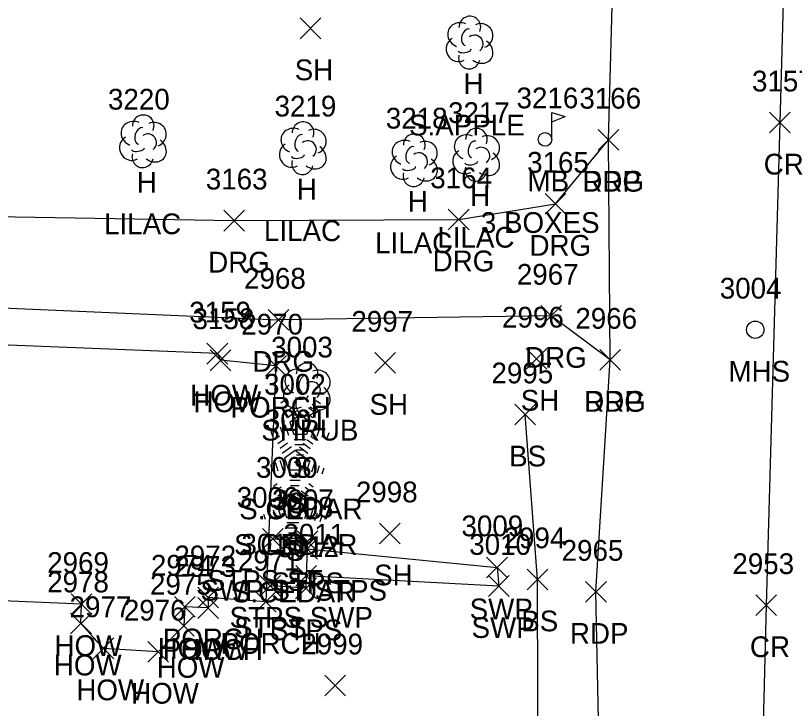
# Model space of a CAD drawing. Extents: x 1609623 to 1616187, y 756677 to 762826.
# Drawn here: x 1610537.9 to 1610613, y 762163.7 to 762230.4 of the extents above; entities that cross this region are included whole.
import ezdxf

# ---------------------------------------------------------------- set-up
doc = ezdxf.new("R2010")
doc.units = 0
for name, color, linetype in [('L_A', 7, 'Continuous'), ('L_C', 7, 'Continuous'), ('L_I', 7, 'Continuous'), ('L_TIC', 7, 'Continuous'), ('LBC', 7, 'Continuous'), ('LBF', 7, 'Continuous'), ('LELB', 7, 'Continuous'), ('LMB', 7, 'Continuous'), ('LSH', 7, 'Continuous'), ('LTC', 7, 'Continuous'), ('LTD', 7, 'Continuous'), ('P_A', 7, 'Continuous'), ('P_I', 7, 'Continuous'), ('P_TIC', 7, 'Continuous'), ('PET', 7, 'Continuous'), ('PRC', 7, 'Continuous'), ('R_A', 7, 'Continuous'), ('R_I', 7, 'Continuous'), ('R_TIC', 7, 'Continuous'), ('RDG', 7, 'Continuous'), ('RSW', 7, 'Continuous'), ('U_A', 7, 'Continuous'), ('U_I', 7, 'Continuous'), ('USMH', 7, 'Continuous')]:
    doc.layers.add(name, color=color, linetype=linetype)

msp = doc.modelspace()

# ---------------------------------------------------------------- linework, layer by layer
at = {"layer": 'L_TIC'}
for points in [[(1610565.324, 762228.161), (1610567.324, 762230.161)], [(1610567.324, 762228.161), (1610565.324, 762230.161)], [(1610556.355, 762196.829), (1610558.355, 762198.829)], [(1610558.355, 762196.829), (1610556.355, 762198.829)], [(1610556.662, 762196.187), (1610558.662, 762198.187)], [(1610558.662, 762196.187), (1610556.662, 762198.187)], [(1610572.533, 762195.938), (1610574.533, 762197.938)], [(1610574.533, 762195.938), (1610572.533, 762197.938)], [(1610587.108, 762196.34), (1610589.108, 762198.34)], [(1610589.108, 762196.34), (1610587.108, 762198.34)], [(1610562.006, 762195.666), (1610564.006, 762197.666)], [(1610564.006, 762195.666), (1610562.006, 762197.666)], [(1610586.033, 762190.967), (1610588.033, 762192.967)], [(1610588.033, 762190.967), (1610586.033, 762192.967)], [(1610572.97, 762179.511), (1610574.97, 762181.511)], [(1610574.97, 762179.511), (1610572.97, 762181.511)], [(1610561.697, 762178.984), (1610563.697, 762180.984)], [(1610563.697, 762178.984), (1610561.697, 762180.984)], [(1610565.046, 762178.757), (1610567.046, 762180.757)], [(1610567.046, 762178.757), (1610565.046, 762180.757)], [(1610565.01, 762178.034), (1610567.01, 762180.034)], [(1610567.01, 762178.034), (1610565.01, 762180.034)], [(1610564.925, 762175.438), (1610566.925, 762177.438)], [(1610566.925, 762175.438), (1610564.925, 762177.438)], [(1610587.202, 762175.086), (1610589.202, 762177.086)], [(1610589.202, 762175.086), (1610587.202, 762177.086)], [(1610561.451, 762174.476), (1610563.451, 762176.476)], [(1610563.451, 762174.476), (1610561.451, 762176.476)], [(1610564.896, 762174.229), (1610566.896, 762176.229)], [(1610566.896, 762174.229), (1610564.896, 762176.229)], [(1610555.476, 762173.348), (1610557.476, 762175.348)], [(1610557.476, 762173.348), (1610555.476, 762175.348)], [(1610543.271, 762172.712), (1610545.271, 762174.712)], [(1610545.271, 762172.712), (1610543.271, 762174.712)], [(1610561.035, 762172.923), (1610563.035, 762174.923)], [(1610563.035, 762172.923), (1610561.035, 762174.923)], [(1610553.216, 762172.447), (1610555.216, 762174.447)], [(1610555.216, 762172.447), (1610553.216, 762174.447)], [(1610555.462, 762172.337), (1610557.462, 762174.337)], [(1610557.462, 762172.337), (1610555.462, 762174.337)], [(1610555.462, 762172.337), (1610557.462, 762174.337)], [(1610557.462, 762172.337), (1610555.462, 762174.337)], [(1610543.214, 762170.839), (1610545.214, 762172.839)], [(1610545.214, 762170.839), (1610543.214, 762172.839)], [(1610553.125, 762170.616), (1610555.125, 762172.616)], [(1610555.125, 762170.616), (1610553.125, 762172.616)], [(1610545.378, 762168.448), (1610547.378, 762170.448)], [(1610547.378, 762168.448), (1610545.378, 762170.448)], [(1610550.658, 762168.122), (1610552.658, 762170.122)], [(1610552.658, 762168.122), (1610550.658, 762170.122)], [(1610567.717, 762164.864), (1610569.717, 762166.864)], [(1610569.717, 762164.864), (1610567.717, 762166.864)]]:
    msp.add_lwpolyline(points, dxfattribs=at)
at = {"layer": 'LBC'}
for points in [[(1610557.662, 762197.187), (1610557.355, 762197.829), (1610526.709, 762199.059)], [(1610544.271, 762173.712), (1610525.977, 762174.475)], [(1610544.214, 762171.839), (1610544.271, 762173.712)], [(1610556.462, 762173.337), (1610554.216, 762173.447), (1610554.125, 762171.616), (1610551.658, 762169.122), (1610546.378, 762169.448), (1610544.214, 762171.839)]]:
    msp.add_lwpolyline(points, dxfattribs=at)
at = {"layer": 'LBF'}
for points in [[(1610563.006, 762196.666), (1610557.662, 762197.187)], [(1610563.006, 762196.666), (1610562.035, 762173.923), (1610556.476, 762174.348), (1610556.462, 762173.337)], [(1610562.697, 762179.984), (1610566.046, 762179.757), (1610566.01, 762179.034), (1610565.925, 762176.438), (1610565.896, 762175.229), (1610562.451, 762175.476)]]:
    msp.add_lwpolyline(points, dxfattribs=at)
at = {"layer": 'LELB'}
msp.add_lwpolyline([(1610588.017, 762127.012), (1610588.281, 762152.993), (1610588.202, 762176.086), (1610587.033, 762191.967)], dxfattribs=at)
at = {"layer": 'LMB'}
for p, q in [((1610589.588, 762221.058), (1610590.881, 762220.676)), ((1610589.594, 762218.465), (1610589.592, 762221.06)), ((1610589.592, 762220.158), (1610590.875, 762220.667)), ((1610588.938, 762218.457), (1610588.938, 762218.457))]:
    msp.add_line(p, q, dxfattribs=at)
msp.add_circle((1610588.938, 762218.457), 0.656, dxfattribs=at)
at = {"layer": 'LSH'}
msp.add_line((1610565.959, 762194.459), (1610565.959, 762194.459), dxfattribs=at)
msp.add_line((1610565.959, 762194.459), (1610565.959, 762194.459), dxfattribs=at)
msp.add_arc((1610566.006, 762195.893), 1.047, 335.52715, 180.95627, dxfattribs=at)
for centre, major_axis, ratio, start_param, end_param in [((1610565.167, 762195.126), (1.21, -0.512), 0.895232, 1.570796, 4.712389), ((1610567.001, 762195.043), (-1.141, -0.483), 0.949671, 1.570796, 4.712389), ((1610565.751, 762194.917), (-0.208, -0.792), 0.645439, 3.141593, 6.283185), ((1610564.876, 762193.751), (0.584, -1.042), 0.959034, 3.141593, 6.283185), ((1610566.459, 762194.293), (-0.5, 0.667), 0.989748, 3.141593, 6.283185), ((1610566.959, 762193.626), (-1.09, 0.792), 0.841452, 1.570796, 4.712389), ((1610565.501, 762193.709), (-0.625, -0.083), 0.423636, 0, 3.141593), ((1610565.959, 762192.959), (0.265, 1.061), 0.942809, 1.570796, 4.712389)]:
    msp.add_ellipse(centre, major_axis=major_axis, ratio=ratio, start_param=start_param, end_param=end_param, dxfattribs=at)
at = {"layer": 'LTC'}
for p, q in [((1610563.474, 762193.083), (1610563.828, 762193.341)), ((1610566.872, 762193.323), (1610567.291, 762193.019)), ((1610563.683, 762192.618), (1610564.212, 762193.002)), ((1610563.893, 762192.152), (1610564.597, 762192.663)), ((1610566.13, 762192.627), (1610566.809, 762192.133)), ((1610566.501, 762192.975), (1610567.05, 762192.576)), ((1610564.102, 762191.686), (1610564.981, 762192.324)), ((1610564.327, 762191.231), (1610565.339, 762191.966)), ((1610565.339, 762191.966), (1610566.336, 762191.241)), ((1610565.759, 762192.278), (1610566.568, 762191.69)), ((1610563.872, 762191.012), (1610564.203, 762189.993)), ((1610564.327, 762191.231), (1610564.714, 762190.038)), ((1610566.336, 762191.241), (1610565.945, 762190.038)), ((1610562.506, 762190.362), (1610562.658, 762189.894)), ((1610562.962, 762190.579), (1610563.173, 762189.927)), ((1610563.417, 762190.796), (1610563.688, 762189.96)), ((1610566.773, 762190.97), (1610566.435, 762189.93)), ((1610567.218, 762190.719), (1610566.93, 762189.835)), ((1610567.662, 762190.469), (1610567.425, 762189.74)), ((1610562.981, 762189.652), (1610563.335, 762189.91)), ((1610563.19, 762189.187), (1610563.719, 762189.571)), ((1610565.945, 762190.038), (1610564.714, 762190.038)), ((1610565.906, 762189.538), (1610564.762, 762189.538)), ((1610566.008, 762189.544), (1610566.557, 762189.145)), ((1610566.379, 762189.893), (1610566.798, 762189.588)), ((1610568.107, 762190.219), (1610567.92, 762189.645)), ((1610563.4, 762188.721), (1610564.104, 762189.232)), ((1610563.609, 762188.255), (1610564.488, 762188.893)), ((1610565.822, 762189.038), (1610564.834, 762189.038)), ((1610565.266, 762188.848), (1610566.075, 762188.259)), ((1610565.637, 762189.196), (1610566.316, 762188.702)), ((1610563.834, 762187.8), (1610564.846, 762188.535)), ((1610564.846, 762188.535), (1610565.843, 762187.81)), ((1610565.739, 762188.538), (1610564.907, 762188.538)), ((1610565.655, 762188.038), (1610564.98, 762188.038)), ((1610562.924, 762187.365), (1610563.195, 762186.529)), ((1610563.379, 762187.581), (1610563.71, 762186.562)), ((1610563.834, 762187.8), (1610564.221, 762186.607)), ((1610565.843, 762187.81), (1610565.451, 762186.607)), ((1610566.28, 762187.539), (1610565.942, 762186.499)), ((1610566.725, 762187.289), (1610566.437, 762186.404)), ((1610562.013, 762186.931), (1610562.165, 762186.464)), ((1610562.469, 762187.148), (1610562.68, 762186.496)), ((1610565.451, 762186.607), (1610564.221, 762186.607)), ((1610567.169, 762187.039), (1610566.932, 762186.309)), ((1610567.614, 762186.788), (1610567.427, 762186.214)), ((1610565.413, 762186.107), (1610564.269, 762186.107)), ((1610562.778, 762185.081), (1610563.133, 762185.339)), ((1610562.988, 762184.616), (1610563.517, 762185)), ((1610565.329, 762185.607), (1610564.341, 762185.607)), ((1610565.246, 762185.107), (1610564.414, 762185.107)), ((1610566.177, 762185.322), (1610566.596, 762185.017)), ((1610563.198, 762184.15), (1610563.901, 762184.661)), ((1610563.407, 762183.684), (1610564.286, 762184.322)), ((1610565.162, 762184.607), (1610564.487, 762184.607)), ((1610565.063, 762184.277), (1610565.873, 762183.688)), ((1610565.435, 762184.625), (1610566.114, 762184.131)), ((1610565.806, 762184.973), (1610566.355, 762184.574)), ((1610563.632, 762183.229), (1610564.643, 762183.964)), ((1610564.643, 762183.964), (1610565.641, 762183.239)), ((1610562.722, 762182.794), (1610562.993, 762181.958)), ((1610563.177, 762183.01), (1610563.508, 762181.991)), ((1610563.632, 762183.229), (1610564.019, 762182.036)), ((1610565.641, 762183.239), (1610565.249, 762182.036)), ((1610566.078, 762182.968), (1610565.74, 762181.928)), ((1610561.811, 762182.36), (1610561.963, 762181.892)), ((1610562.266, 762182.577), (1610562.478, 762181.925)), ((1610565.249, 762182.036), (1610564.019, 762182.036)), ((1610566.523, 762182.717), (1610566.235, 762181.833)), ((1610566.967, 762182.467), (1610566.73, 762181.738)), ((1610567.411, 762182.217), (1610567.225, 762181.643)), ((1610565.211, 762181.536), (1610564.066, 762181.536)), ((1610565.127, 762181.036), (1610564.139, 762181.036)), ((1610565.043, 762180.536), (1610564.212, 762180.536)), ((1610564.96, 762180.036), (1610564.285, 762180.036))]:
    msp.add_line(p, q, dxfattribs=at)
at = {"layer": 'LTD'}
for p, q in [((1610581.643, 762227.839), (1610581.643, 762227.839)), ((1610581.643, 762227.839), (1610581.643, 762227.839)), ((1610550.163, 762218.332), (1610550.163, 762218.332)), ((1610550.163, 762218.332), (1610550.163, 762218.332)), ((1610565.573, 762217.667), (1610565.573, 762217.667)), ((1610565.573, 762217.667), (1610565.573, 762217.667)), ((1610582.28, 762217.04), (1610582.28, 762217.04)), ((1610582.28, 762217.04), (1610582.28, 762217.04)), ((1610576.284, 762216.505), (1610576.284, 762216.505)), ((1610576.284, 762216.505), (1610576.284, 762216.505))]:
    msp.add_line(p, q, dxfattribs=at)
for centre in [(1610581.69, 762229.273), (1610550.21, 762219.766), (1610565.62, 762219.1), (1610582.327, 762218.474), (1610576.331, 762217.939)]:
    msp.add_arc(centre, 1.047, 335.52715, 180.95627, dxfattribs=at)
for centre, major_axis, ratio, start_param, end_param in [((1610580.851, 762228.506), (1.21, -0.512), 0.895232, 1.570796, 4.712389), ((1610582.685, 762228.423), (-1.141, -0.483), 0.949671, 1.570796, 4.712389), ((1610581.435, 762228.298), (-0.208, -0.792), 0.645439, 3.141593, 6.283185), ((1610582.143, 762227.673), (-0.5, 0.667), 0.989748, 3.141593, 6.283185), ((1610580.56, 762227.131), (0.584, -1.042), 0.959034, 3.141593, 6.283185), ((1610582.643, 762227.006), (-1.09, 0.792), 0.841452, 1.570796, 4.712389), ((1610581.185, 762227.089), (-0.625, -0.083), 0.423636, 0, 3.141593), ((1610581.643, 762226.339), (0.265, 1.061), 0.942809, 1.570796, 4.712389), ((1610549.372, 762218.998), (1.21, -0.512), 0.895232, 1.570796, 4.712389), ((1610549.955, 762218.79), (-0.208, -0.792), 0.645439, 3.141593, 6.283185), ((1610551.205, 762218.915), (-1.141, -0.483), 0.949671, 1.570796, 4.712389), ((1610564.781, 762218.333), (1.21, -0.512), 0.895232, 1.570796, 4.712389), ((1610566.615, 762218.25), (-1.141, -0.483), 0.949671, 1.570796, 4.712389), ((1610550.663, 762218.165), (-0.5, 0.667), 0.989748, 3.141593, 6.283185), ((1610565.365, 762218.125), (-0.208, -0.792), 0.645439, 3.141593, 6.283185), ((1610581.488, 762217.706), (1.21, -0.512), 0.895232, 1.570796, 4.712389), ((1610583.321, 762217.623), (-1.141, -0.483), 0.949671, 1.570796, 4.712389), ((1610549.08, 762217.623), (0.584, -1.042), 0.959034, 3.141593, 6.283185), ((1610551.164, 762217.499), (-1.09, 0.792), 0.841452, 1.570796, 4.712389), ((1610566.073, 762217.5), (-0.5, 0.667), 0.989748, 3.141593, 6.283185), ((1610575.492, 762217.172), (1.21, -0.512), 0.895232, 1.570796, 4.712389), ((1610577.325, 762217.089), (-1.141, -0.483), 0.949671, 1.570796, 4.712389), ((1610582.071, 762217.498), (-0.208, -0.792), 0.645439, 3.141593, 6.283185), ((1610549.705, 762217.582), (-0.625, -0.083), 0.423636, 0, 3.141593), ((1610564.49, 762216.958), (0.584, -1.042), 0.959034, 3.141593, 6.283185), ((1610566.573, 762216.833), (-1.09, 0.792), 0.841452, 1.570796, 4.712389), ((1610576.075, 762216.964), (-0.208, -0.792), 0.645439, 3.141593, 6.283185), ((1610576.784, 762216.339), (-0.5, 0.667), 0.989748, 3.141593, 6.283185), ((1610581.197, 762216.331), (0.584, -1.042), 0.959034, 3.141593, 6.283185), ((1610582.78, 762216.873), (-0.5, 0.667), 0.989748, 3.141593, 6.283185), ((1610550.164, 762216.832), (0.265, 1.061), 0.942809, 1.570796, 4.712389), ((1610565.115, 762216.916), (-0.625, -0.083), 0.423636, 0, 3.141593), ((1610575.201, 762215.797), (0.584, -1.042), 0.959034, 3.141593, 6.283185), ((1610577.284, 762215.672), (-1.09, 0.792), 0.841452, 1.570796, 4.712389), ((1610583.28, 762216.206), (-1.09, 0.792), 0.841452, 1.570796, 4.712389), ((1610565.573, 762216.167), (0.265, 1.061), 0.942809, 1.570796, 4.712389), ((1610575.826, 762215.755), (-0.625, -0.083), 0.423636, 0, 3.141593), ((1610582.28, 762215.54), (0.265, 1.061), 0.942809, 1.570796, 4.712389), ((1610581.822, 762216.289), (-0.625, -0.083), 0.423636, 0, 3.141593), ((1610576.284, 762215.005), (0.265, 1.061), 0.942809, 1.570796, 4.712389)]:
    msp.add_ellipse(centre, major_axis=major_axis, ratio=ratio, start_param=start_param, end_param=end_param, dxfattribs=at)
at = {"layer": 'P_TIC'}
for points in [[(1610610.575, 762219.08), (1610612.575, 762221.08)], [(1610612.575, 762219.08), (1610610.575, 762221.08)], [(1610594.042, 762217.426), (1610596.042, 762219.426)], [(1610596.042, 762217.426), (1610594.042, 762219.426)], [(1610594.221, 762196.229), (1610596.221, 762198.229)], [(1610596.221, 762196.229), (1610594.221, 762198.229)], [(1610592.846, 762173.883), (1610594.846, 762175.883)], [(1610594.846, 762173.883), (1610592.846, 762175.883)], [(1610609.25, 762172.6), (1610611.25, 762174.6)], [(1610611.25, 762172.6), (1610609.25, 762174.6)]]:
    msp.add_lwpolyline(points, dxfattribs=at)
at = {"layer": 'PET'}
for points in [[(1610595.042, 762218.426), (1610595.917, 762249.995), (1610597.031, 762268.03), (1610599.193, 762317.836), (1610601.019, 762361.918), (1610601.974, 762392.041), (1610603.581, 762435.722)], [(1610595.221, 762197.229), (1610595.042, 762218.426)], [(1610585.692, 762059.184), (1610595.53, 762075.623), (1610597.332, 762109.675), (1610594.5, 762142.599), (1610593.846, 762174.883), (1610595.221, 762197.229)]]:
    msp.add_lwpolyline(points, dxfattribs=at)
at = {"layer": 'PRC'}
for points in [[(1610616.879, 762447.816), (1610616.899, 762397.767), (1610615.755, 762350.31), (1610614.292, 762312.677), (1610612.908, 762268.601), (1610611.575, 762220.08)], [(1610611.575, 762220.08), (1610610.25, 762173.6)], [(1610610.25, 762173.6), (1610609.383, 762139.192), (1610609.124, 762094.71), (1610608.211, 762046.285), (1610607.395, 761995.029), (1610607.457, 761942.783), (1610607.989, 761912.156), (1610611.007, 761877.324)]]:
    msp.add_lwpolyline(points, dxfattribs=at)
at = {"layer": 'R_TIC'}
for points in [[(1610594.042, 762217.426), (1610596.042, 762219.426)], [(1610596.042, 762217.426), (1610594.042, 762219.426)], [(1610588.951, 762211.253), (1610590.951, 762213.253)], [(1610590.951, 762211.253), (1610588.951, 762213.253)], [(1610557.985, 762209.639), (1610559.985, 762211.639)], [(1610559.985, 762209.639), (1610557.985, 762211.639)], [(1610579.614, 762209.756), (1610581.614, 762211.756)], [(1610581.614, 762209.756), (1610579.614, 762211.756)], [(1610588.527, 762200.466), (1610590.527, 762202.466)], [(1610590.527, 762200.466), (1610588.527, 762202.466)], [(1610562.239, 762200.083), (1610564.239, 762202.083)], [(1610564.239, 762200.083), (1610562.239, 762202.083)], [(1610594.221, 762196.229), (1610596.221, 762198.229)], [(1610596.221, 762196.229), (1610594.221, 762198.229)], [(1610565.01, 762178.034), (1610567.01, 762180.034)], [(1610567.01, 762178.034), (1610565.01, 762180.034)], [(1610583.308, 762176.243), (1610585.308, 762178.243)], [(1610585.308, 762176.243), (1610583.308, 762178.243)], [(1610564.925, 762175.438), (1610566.925, 762177.438)], [(1610566.925, 762175.438), (1610564.925, 762177.438)], [(1610583.493, 762174.45), (1610585.493, 762176.45)], [(1610585.493, 762174.45), (1610583.493, 762176.45)]]:
    msp.add_lwpolyline(points, dxfattribs=at)
at = {"layer": 'RDG'}
for points in [[(1610526.959, 762202.645), (1610528.28, 762211.152), (1610558.985, 762210.639), (1610580.614, 762210.756), (1610589.951, 762212.253), (1610595.042, 762218.426)], [(1610526.959, 762202.645), (1610563.239, 762201.083)], [(1610595.221, 762197.229), (1610589.527, 762201.466), (1610563.239, 762201.083)]]:
    msp.add_lwpolyline(points, dxfattribs=at)
at = {"layer": 'RSW'}
msp.add_lwpolyline([(1610566.01, 762179.034), (1610584.308, 762177.243), (1610584.493, 762175.45), (1610565.925, 762176.438)], dxfattribs=at)
at = {"layer": 'USMH'}
for p, q in [((1610609.195, 762200.133), (1610609.195, 762200.133)), ((1610610.028, 762200.133), (1610610.028, 762200.133))]:
    msp.add_line(p, q, dxfattribs=at)
msp.add_circle((1610609.195, 762200.133), 0.833, dxfattribs=at)

# ---------------------------------------------------------------- texts
at = {"layer": 'L_A'}
for s, p in [('SH', (1610564.812, 762224.161)), ('H', (1610581.076, 762222.839)), ('H', (1610549.596, 762213.332)), ('MB', (1610587.245, 762213.457)), ('H', (1610565.006, 762212.667)), ('H', (1610581.713, 762212.04)), ('H', (1610575.717, 762211.505)), ('HOW', (1610554.741, 762192.829)), ('HOW', (1610555.048, 762192.187)), ('SH', (1610586.596, 762192.34)), ('PORCH', (1610558.628, 762191.666)), ('SH', (1610572.021, 762191.938)), ('SHRUB', (1610561.589, 762189.459)), ('BS', (1610585.474, 762186.967)), ('S', (1610564.664, 762185.875)), ('S', (1610564.171, 762182.444)), ('S', (1610563.969, 762177.873)), ('SH', (1610572.458, 762175.511)), ('STPS ST', (1610556.342, 762174.984)), ('STPS', (1610562.566, 762174.757)), ('SWP ST STPS', (1610555.726, 762174.034)), ('STPS SWP', (1610558.531, 762171.438)), ('BS', (1610586.643, 762171.086)), ('STPS', (1610558.971, 762170.476)), ('STPS', (1610562.416, 762170.229)), ('HOW', (1610541.657, 762168.712)), ('PORCH', (1610552.098, 762169.348)), ('PORCH', (1610557.657, 762168.923)), ('HOW', (1610551.602, 762168.447)), ('PORCH', (1610552.084, 762168.337)), ('HOW', (1610553.847, 762168.337)), ('HOW', (1610541.599, 762166.839)), ('HOW', (1610551.511, 762166.616)), ('HOW', (1610543.764, 762164.448)), ('HOW', (1610549.044, 762164.122))]:
    msp.add_text(s, height=2, dxfattribs=at).set_placement(p)
at = {"layer": 'L_C'}
for s, p in [('S.APPLE', (1610575.832, 762218.839)), ('LILAC', (1610546.439, 762209.332)), ('3 BOXES', (1610582.749, 762209.457)), ('LILAC', (1610561.849, 762208.667)), ('LILAC', (1610578.555, 762208.04)), ('LILAC', (1610572.559, 762207.505)), ('S.CEDAR', (1610559.46, 762181.875)), ('S.CEDAR', (1610558.967, 762178.444)), ('S.CEDAR', (1610558.764, 762173.873))]:
    msp.add_text(s, height=2, dxfattribs=at).set_placement(p)
at = {"layer": 'L_I'}
for s, p in [('3220', (1610546.817, 762221.332)), ('3216', (1610586.19, 762221.457)), ('3219', (1610562.872, 762220.667)), ('3217', (1610579.587, 762220.04)), ('3218', (1610573.591, 762219.505)), ('3159', (1610554.654, 762200.829)), ('2996', (1610584.793, 762200.34)), ('3158', (1610554.969, 762200.187)), ('2970', (1610559.659, 762199.666)), ('2997', (1610570.273, 762199.938)), ('3003', (1610562.542, 762197.459)), ('2995', (1610583.773, 762194.967)), ('3002', (1610561.861, 762193.875)), ('3001', (1610561.935, 762190.444)), ('3000', (1610561.079, 762185.873)), ('3006', (1610559.224, 762182.984)), ('2998', (1610570.71, 762183.511)), ('3007', (1610562.629, 762182.757)), ('3008', (1610562.592, 762182.034)), ('3011', (1610563.72, 762179.438)), ('3013', (1610559.679, 762178.476)), ('2994', (1610584.943, 762179.086)), ('3012', (1610563.125, 762178.229)), ('2972', (1610553.216, 762177.348)), ('2969', (1610540.956, 762176.712)), ('2974', (1610550.956, 762176.447)), ('2973', (1610553.202, 762176.337)), ('2973', (1610553.202, 762176.337)), ('2971', (1610559.342, 762176.923)), ('2978', (1610540.954, 762174.839)), ('2975', (1610550.865, 762174.616)), ('2977', (1610543.118, 762172.448)), ('2976', (1610548.343, 762172.122)), ('2999', (1610565.449, 762168.864))]:
    msp.add_text(s, height=2, dxfattribs=at).set_placement(p)
at = {"layer": 'LTC'}
for p in [(1610565.221, 762190.979), (1610564.728, 762187.548), (1610564.526, 762182.977)]:
    msp.add_text('.', height=1.037, rotation=270, dxfattribs=at).set_placement(p)
at = {"layer": 'P_A'}
for s, p in [('CR', (1610610.008, 762215.08)), ('RDP', (1610592.53, 762213.426)), ('RDP', (1610592.709, 762192.229)), ('RDP', (1610591.334, 762169.883)), ('CR', (1610608.683, 762168.6))]:
    msp.add_text(s, height=2, dxfattribs=at).set_placement(p)
at = {"layer": 'P_I'}
for s, p in [('3157', (1610608.882, 762223.08)), ('3166', (1610592.247, 762221.426)), ('2966', (1610591.859, 762200.229)), ('2965', (1610590.539, 762177.883)), ('2953', (1610606.99, 762176.6))]:
    msp.add_text(s, height=2, dxfattribs=at).set_placement(p)
at = {"layer": 'R_A'}
for s, p in [('DRG', (1610592.53, 762213.426)), ('DRG', (1610587.439, 762207.253)), ('DRG', (1610556.473, 762205.639)), ('DRG', (1610578.102, 762205.756)), ('DRG', (1610560.727, 762196.083)), ('DRG', (1610587.015, 762196.466)), ('DRG', (1610592.709, 762192.229)), ('SWP ST STPS', (1610555.726, 762174.034)), ('SWP', (1610581.671, 762172.243)), ('STPS SWP', (1610558.531, 762171.438)), ('SWP', (1610581.855, 762170.45))]:
    msp.add_text(s, height=2, dxfattribs=at).set_placement(p)
at = {"layer": 'R_I'}
for s, p in [('3166', (1610592.247, 762221.426)), ('3165', (1610587.211, 762215.253)), ('3164', (1610577.874, 762213.756)), ('3163', (1610556.244, 762213.639)), ('2968', (1610559.932, 762204.083)), ('2967', (1610586.22, 762204.466)), ('2966', (1610591.859, 762200.229)), ('3008', (1610562.592, 762182.034)), ('3009', (1610580.883, 762180.243)), ('3011', (1610563.72, 762179.438)), ('3010', (1610581.634, 762178.45))]:
    msp.add_text(s, height=2, dxfattribs=at).set_placement(p)
at = {"layer": 'U_A'}
msp.add_text('MHS', height=2, dxfattribs=at).set_placement((1610606.612, 762195.133))
at = {"layer": 'U_I'}
msp.add_text('3004', height=2, dxfattribs=at).set_placement((1610605.777, 762203.133))

doc.saveas('drawing.dxf')
